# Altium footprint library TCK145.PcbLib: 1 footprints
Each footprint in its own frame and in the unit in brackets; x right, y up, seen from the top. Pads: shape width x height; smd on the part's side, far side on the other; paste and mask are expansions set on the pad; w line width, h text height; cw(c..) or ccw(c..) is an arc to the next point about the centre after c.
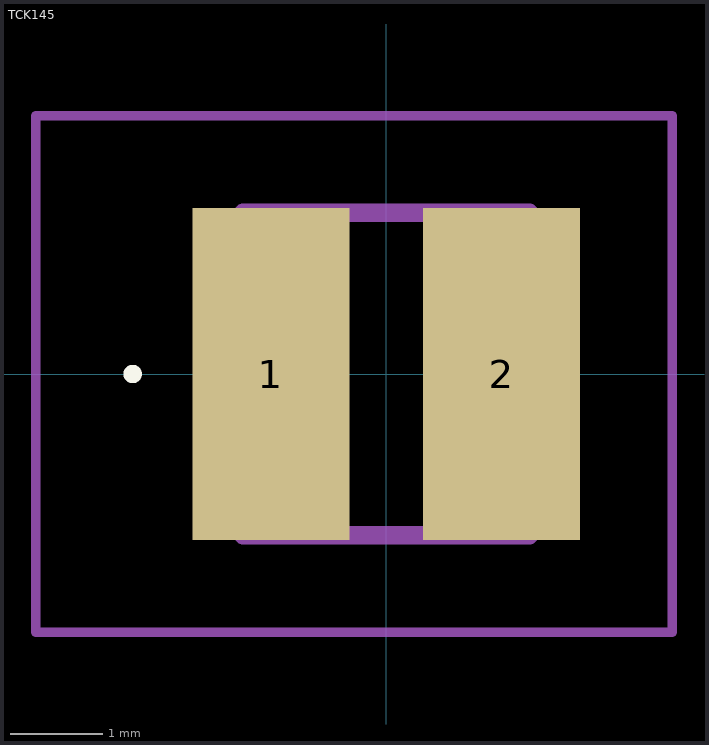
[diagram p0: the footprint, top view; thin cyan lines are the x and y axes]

## TCK145 [mm]
pads (2):
  rect 1.7x3.6 smd: 1(-1.25,0) 2(1.25,0)
Top Overlay:
  lines w0.1: -2.8,0 -2.8,0 ; -2.8,0 ccw(c-2.75,0) -2.7,0 ; -2.8,0 cw(c-2.75,0) -2.7,0 ; -2.7,0 -2.7,0
Mechanical 15:
  lines w0.2: -1.55,-1.75 1.55,-1.75 1.55,1.75 -1.55,1.75 -1.55,-1.75
Mechanical 20:
  lines w0.1: -3.8,-2.8 3.1,-2.8 3.1,2.8 -3.8,2.8 -3.8,-2.8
